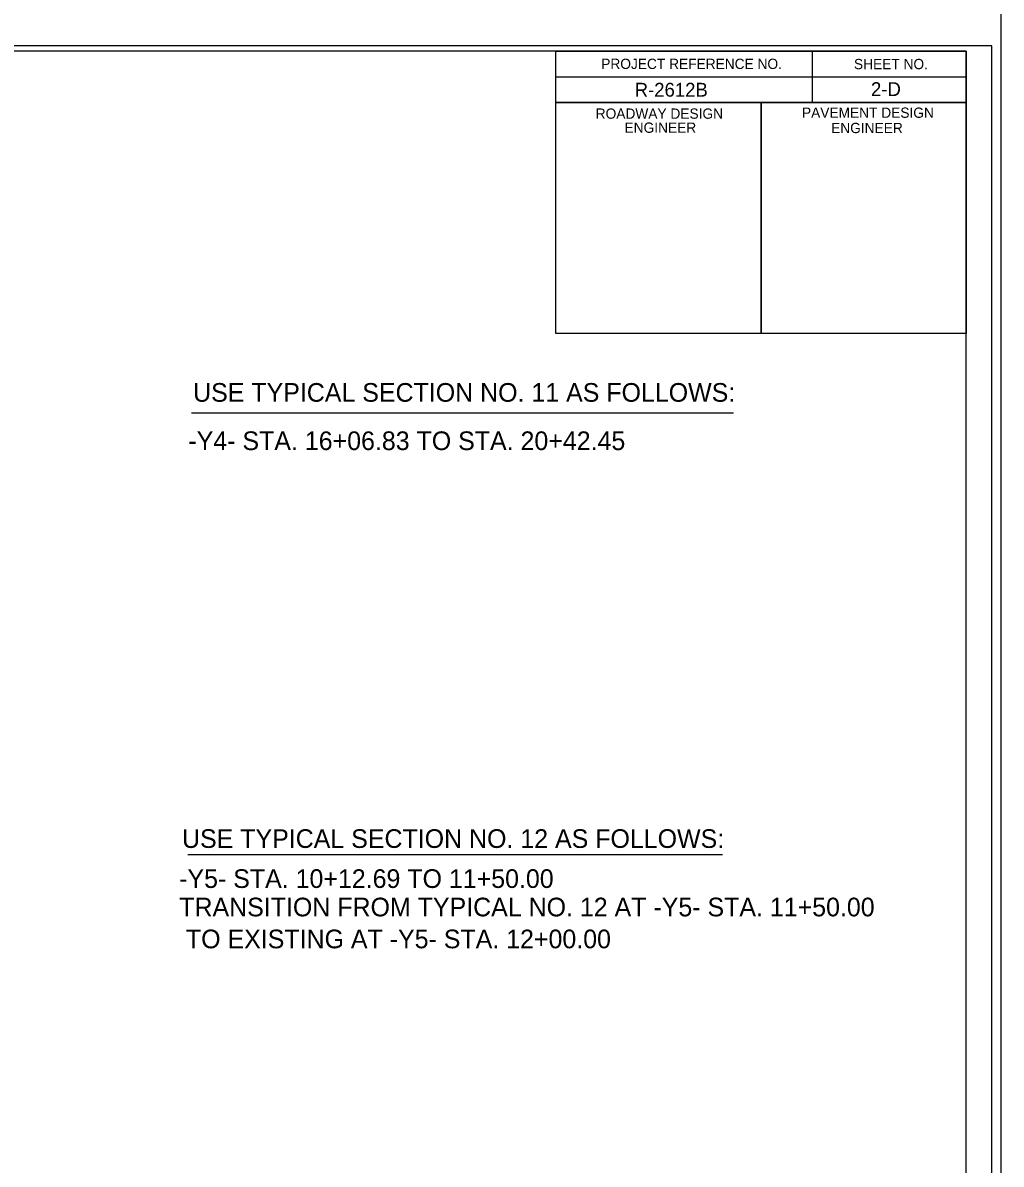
# Model space of a CAD drawing. Extents: x 573813 to 575363, y -54752 to -53123.
# Drawn here: x 574911.3 to 575006.7, y -54116.8 to -54005.6 of the extents above; entities that cross this region are included whole.
import ezdxf

# ---------------------------------------------------------------- set-up
doc = ezdxf.new("R2010")
doc.units = 0
for name, color, linetype in [('Old_Level_1', 7, 'Continuous'), ('Old_Level_11', 7, 'Continuous'), ('Sheet Data Field CELL', 7, 'Continuous'), ('Sheet Plot Border Inside CELL', 7, 'Continuous'), ('Sheet Plot Border Outside CELL', 7, 'Continuous'), ('Sheet Typical CELL', 7, 'Continuous')]:
    doc.layers.add(name, color=color, linetype=linetype)

msp = doc.modelspace()

# ---------------------------------------------------------------- linework, layer by layer
at = {"layer": 'Old_Level_11'}
for p, q in [((574927.77, -54043.56), (574980.61, -54043.56)), ((574927.41, -54086.6), (574979.54, -54086.6))]:
    msp.add_line(p, q, dxfattribs=at)
at = {"layer": 'Sheet Plot Border Inside CELL'}
msp.add_lwpolyline([(575005.81, -54007.8), (574672.33, -54007.8), (574672.33, -54218.93), (575005.81, -54218.93)], close=True, dxfattribs=at)
at = {"layer": 'Sheet Plot Border Outside CELL'}
msp.add_line((575006.71, -54223.42), (575006.71, -54003.31), dxfattribs=at)
msp.add_lwpolyline([(575006.71, -54003.31), (574669.73, -54003.31), (574669.73, -54223.42), (575006.71, -54223.42)], close=True, dxfattribs=at)
at = {"layer": 'Sheet Typical CELL'}
for p, q in [((574988.3, -54008.32), (574988.3, -54013.32)), ((574963.28, -54010.82), (575003.31, -54010.82)), ((574983.3, -54013.32), (574983.3, -54035.82))]:
    msp.add_line(p, q, dxfattribs=at)
for points in [[(575003.31, -54008.31), (574703.15, -54008.31), (574703.15, -54218.42), (575003.31, -54218.42)], [(574963.28, -54008.31), (575003.31, -54008.31), (575003.31, -54013.32), (574963.28, -54013.32)], [(574963.28, -54013.32), (574983.3, -54013.32), (574983.3, -54035.83), (574963.28, -54035.83)], [(574983.3, -54013.32), (575003.31, -54013.32), (575003.31, -54035.83), (574983.3, -54035.83)]]:
    msp.add_lwpolyline(points, close=True, dxfattribs=at)

# ---------------------------------------------------------------- texts
at = {"layer": 'Old_Level_1'}
for s, rotation, p in [('USE TYPICAL SECTION NO. 11 AS FOLLOWS:', 360, (574927.93, -54042.48)), ('-Y4- STA. 16+06.83 TO STA. 20+42.45', 0, (574927.47, -54047.19)), ('USE TYPICAL SECTION NO. 12 AS FOLLOWS:', 360, (574926.85, -54085.96)), ('-Y5- STA. 10+12.69 TO 11+50.00', 0, (574926.57, -54089.86)), ('TRANSITION FROM TYPICAL NO. 12 AT -Y5- STA. 11+50.00', 0, (574926.58, -54092.63)), ('TO EXISTING AT -Y5- STA. 12+00.00', 0, (574927.23, -54095.74))]:
    msp.add_text(s, height=1.8192, rotation=rotation, dxfattribs=at).set_placement(p)
at = {"layer": 'Sheet Data Field CELL'}
for s, p in [('R-2612B  ', (574970.98, -54012.75)), ('2-D', (574994.02, -54012.69))]:
    msp.add_text(s, height=1.351, dxfattribs=at).set_placement(p)
at = {"layer": 'Sheet Typical CELL'}
for s, height, p in [('PROJECT REFERENCE NO.', 1.0006, (574967.72, -54010.05)), ('SHEET NO.', 1.001, (574992.36, -54010.07)), ('ROADWAY DESIGN', 1.0006, (574967.18, -54014.9)), ('PAVEMENT DESIGN', 1.0006, (574987.29, -54014.81)), ('ENGINEER', 1.001, (574969.99, -54016.27)), ('ENGINEER', 1.001, (574990.13, -54016.3))]:
    msp.add_text(s, height=height, dxfattribs=at).set_placement(p)

doc.saveas('drawing.dxf')
